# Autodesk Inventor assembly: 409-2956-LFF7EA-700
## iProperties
Created: 2010-06
Part Number: 409-2956-LFF7EA-700
Document SubType Name: Assembly
Designer: S. Boerckel
Mass: 2.77514e+06 g
Surface Area: 742601 cm^2
Volume: 368410 cm^3
Density: 7.53275 g/cm^3
Description: MECHANICAL
Material: ASSEMBLY
Author: S. Boerckel
Revision Number: B
Title: MECHANICAL
Subject: LIQUID FUEL FORWARDING PUMP SKID-7EA
